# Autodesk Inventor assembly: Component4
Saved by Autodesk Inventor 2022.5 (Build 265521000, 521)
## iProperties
Created: 2024-12
Part Number: Component4
Document SubType Name: Assembly
Designer: AdminForWorker
Title: Component4
Author: AdminForWorker
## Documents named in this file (2)
- c:\worker\convert-fusion-r05-cosv3\tmp\job-1\35\temp\files\545dca92-a972-481a-9197-dd1a1176500e\Component4.iam
- c:\worker\convert-fusion-r05-cosv3\tmp\job-1\35\temp\files\545dca92-a972-481a-9197-dd1a1176500e\Component5.ipt
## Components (1 placed, 1 different names)
1. Component5:1
